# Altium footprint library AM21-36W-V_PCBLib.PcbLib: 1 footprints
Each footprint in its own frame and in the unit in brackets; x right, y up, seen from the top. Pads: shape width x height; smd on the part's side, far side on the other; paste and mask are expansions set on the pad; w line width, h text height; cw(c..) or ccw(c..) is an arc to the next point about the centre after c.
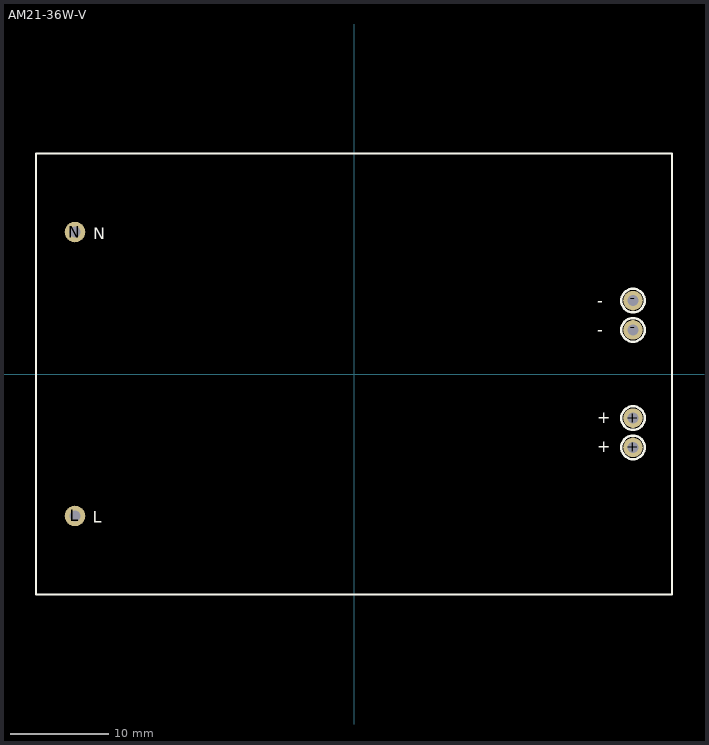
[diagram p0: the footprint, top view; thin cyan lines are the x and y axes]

## AM21-36W-V [mm]
pads (6):
  round 2 hole 1.1: +(28.5,-7.5) +(28.5,-4.5) -(28.5,4.5) -(28.5,7.5)
  round 2.1 hole 1.1: L(-28.5,-14.5) N(-28.5,14.5)
TopOverlay:
  circle w0.254: c28.5,7.5 r1.2
  circle w0.254: c28.5,4.5 r1.2
  circle w0.254: c28.5,-4.5 r1.2
  circle w0.254: c28.5,-7.5 r1.2
  lines w0.2: -32.5,-22.5 -32.5,22.5 32.5,22.5 32.5,-22.5 -32.5,-22.5
  text "N" at -26.65,13.75 h1.2
  text "L" at -26.694,-15.183 h1.2
  text "+" at 24.856,-7.983 h1.2
  text "+" at 24.856,-5.033 h1.2
  text "-" at 24.856,3.967 h1.2
  text "-" at 24.856,6.917 h1.2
